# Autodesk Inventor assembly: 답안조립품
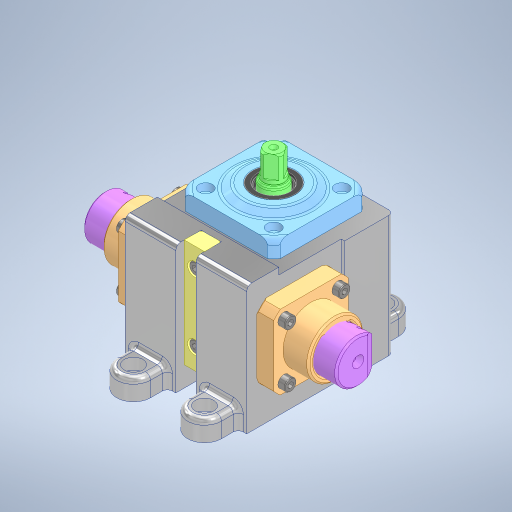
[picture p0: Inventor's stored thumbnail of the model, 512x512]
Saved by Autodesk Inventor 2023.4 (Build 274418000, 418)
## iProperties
Created: 2024-11
Part Number: 답안조립품
Document SubType Name: Assembly
Designer: EDU-001
Author: EDU-001
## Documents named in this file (10)
- C:\Users\EDU-001\Desktop\741104V1016\741104V1016\답안조립품.iam
- C:\Users\EDU-001\Desktop\741104V1016\본체.ipt
- C:\Users\EDU-001\Desktop\741104V1016 (2)\깊음 홈 볼 베어링 6202\깊음 홈 볼 베어링 6202.ipt
- C:\Users\EDU-001\Desktop\741104V1016 (2)\피니언 축\피니언 축.ipt
- C:\Users\EDU-001\Desktop\741104V1016 (2)\커버\커버.ipt
- C:\Users\EDU-001\Desktop\741104V1016 (2)\오일 실 15 25 4\오일 실 15 25 4.ipt
- C:\Users\EDU-001\Desktop\741104V1016 (2)\래크\래크.ipt
- C:\Users\EDU-001\Desktop\741104V1016 (2)\스톱퍼\스톱퍼.ipt
- C:\Users\EDU-001\Desktop\741104V1016 (2)\수지 부시\수지 부시.ipt
- C:\Users\EDU-001\Desktop\741104V1016 (2)\육각 소켓 머리 볼트 M4x10\육각 소켓 머리 볼트 M4x10.ipt
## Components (1 placed, 1 different names)
1. 피니언 축:1 — 각도:1
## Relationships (1: Angle 1)
- 각도:1 [Angle]: 피니언 축:1
